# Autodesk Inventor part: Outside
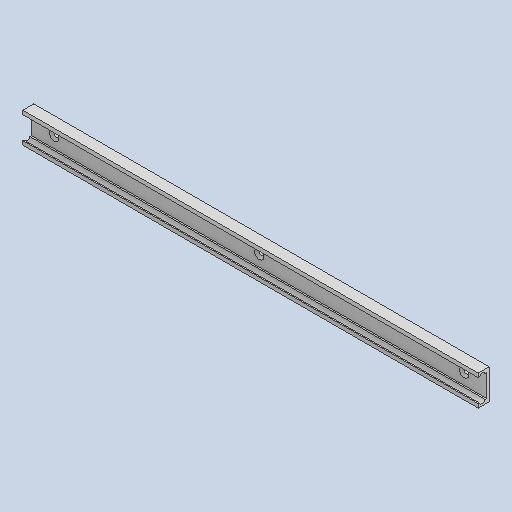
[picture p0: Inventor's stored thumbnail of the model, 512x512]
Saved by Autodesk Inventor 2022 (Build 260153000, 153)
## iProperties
Created: 2021-09
Part Number: Outside
Material: Generic
Document SubType Name: Modeling
Designer: deli
Density: 1 g/cm^3
Appearance: Default
Author: deli
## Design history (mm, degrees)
sketch "Sketch1"
  geometry: L1 (50.649, -6.18)-(53.249, -6.18); L2 (53.249, -6.18)-(53.249, -13.38); L3 (50.649, -6.18)-(50.649, -6.9); L4 (50.649, -10.86)-(50.649, -11.88); L5 (50.649, -11.88)-(35.849, -11.88); L6 (53.249, -13.38)-(33.249, -13.38); L7 (33.249, -13.38)-(33.249, -6.18); L8 (33.249, -6.18)-(35.849, -6.18); L9 (35.849, -6.18)-(35.849, -6.9); L10 (35.849, -10.86)-(35.849, -11.88); A1 r 2.1 centre (49.949, -8.88) between (50.649, -10.86) and (50.649, -6.9); A2 r 2.1 centre (36.549, -8.88) between (35.849, -6.9) and (35.849, -10.86); 1 further point
  constraints: 20 end point, 4 point on circle, 2 centre point
extrude "Extrusion1" new body sketch "Sketch1" distance "d0" = 300; taper "d1" = 0 deg
sketch "Sketch2"
  geometry: C1 r 1.6 at (285, 7.4) reference; C2 r 1.6 at (150, 7.4) reference; C3 r 1.6 at (15, 7.4) reference; 1 further point
extrude "Extrusion2" cut sketch "Sketch2" distance "d2" = 300; taper "d3" = 0 deg
chamfer "Chamfer1" distance "d4" = 1.5; stored, may be unused: second distance "d5" = 1.5, angle "d6" = 45 deg
body "Solid1"
node "Reference13"
node "Reference14"
node "Reference15"
